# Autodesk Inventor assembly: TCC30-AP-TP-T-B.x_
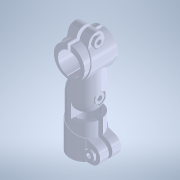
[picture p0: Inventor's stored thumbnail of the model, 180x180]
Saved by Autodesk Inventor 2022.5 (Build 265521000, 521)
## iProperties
Created: 2023-09
Part Number: TCC30-AP-TP-T-B.x_
Document SubType Name: Assembly
Designer: ImaoCorp
Sending System: SOLIDWORKS 2021-2021301
MC: AMD64
MC_MODEL: Intel64 Family 6 Model 60 Stepping 3, GenuineIntel
OS: Windows_NT
FRU: Parasolid Version 32.1, build 255,  1- 1-2021
FORMAT: text
GUISE: transmit
KEY: TCC30-AP-TP-T-B
FILE: TCC30-AP-TP-T-B.x_t
DATE: Fri Sep 15 15:36:30 2023
Author: ImaoCorp
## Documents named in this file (9)
- X:\14_SW2022-Inv2022\00_全2023-1023新製品(TCC)まで\t\tcc30-ap-tp-t-b\TCC30-AP-TP-T-B.iam
- X:\14_SW2022-Inv2022\00_全2023-1023新製品(TCC)まで\t\tcc30-ap-tp-t-b\TCC30-AP-TP-T-B_01.ipt
- X:\14_SW2022-Inv2022\00_全2023-1023新製品(TCC)まで\t\tcc30-ap-tp-t-b\TCC30-AP-TP-T-B_02.ipt
- X:\14_SW2022-Inv2022\00_全2023-1023新製品(TCC)まで\t\tcc30-ap-tp-t-b\TCC30-AP-TP-T-B_03.ipt
- X:\14_SW2022-Inv2022\00_全2023-1023新製品(TCC)まで\t\tcc30-ap-tp-t-b\TCC30-AP-TP-T-B_04.ipt
- X:\14_SW2022-Inv2022\00_全2023-1023新製品(TCC)まで\t\tcc30-ap-tp-t-b\TCC30-AP-TP-T-B_05.ipt
- X:\14_SW2022-Inv2022\00_全2023-1023新製品(TCC)まで\t\tcc30-ap-tp-t-b\TCC30-AP-TP-T-B_06.ipt
- X:\14_SW2022-Inv2022\00_全2023-1023新製品(TCC)まで\t\tcc30-ap-tp-t-b\TCC30-AP-TP-T-B_07.ipt
- X:\14_SW2022-Inv2022\00_全2023-1023新製品(TCC)まで\t\tcc30-ap-tp-t-b\TCC30-AP-TP-T-B_08.ipt
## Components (8 placed, 8 different names)
1. TCC30-AP-TP-T-B_01
2. TCC30-AP-TP-T-B_02
3. TCC30-AP-TP-T-B_03
4. TCC30-AP-TP-T-B_04
5. TCC30-AP-TP-T-B_05
6. TCC30-AP-TP-T-B_06
7. TCC30-AP-TP-T-B_07
8. TCC30-AP-TP-T-B_08
